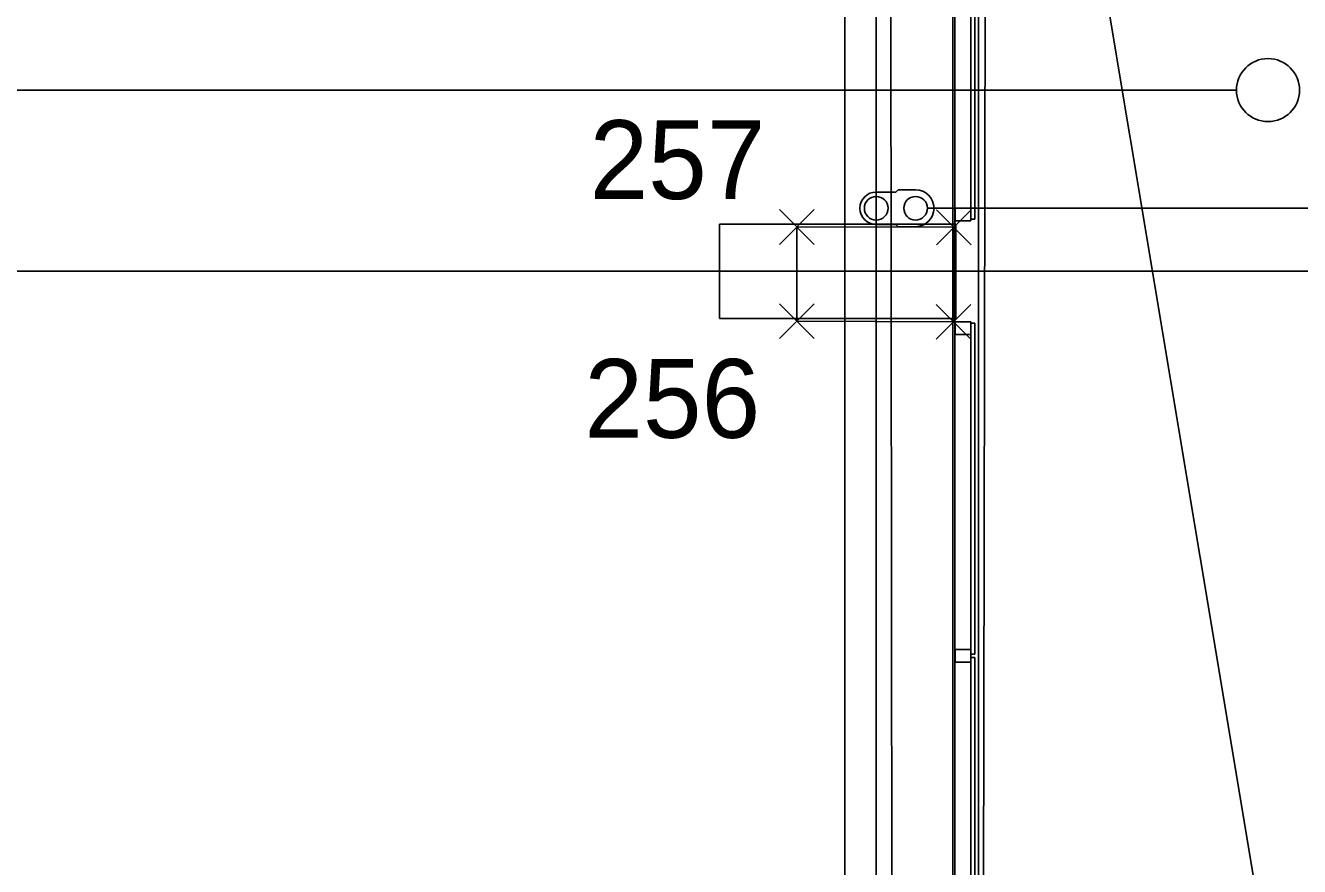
# Model space of a CAD drawing. Extents: x -264205 to -263659, y -1242401 to -1242060.
# Drawn here: x -263800.94 to -263792.86, y -1242178.66 to -1242173.32 of the extents above; entities that cross this region are included whole.
import ezdxf

# ---------------------------------------------------------------- set-up
doc = ezdxf.new("R2010")
doc.units = 0
for name, color, linetype in [('BOD_CISLO', 7, 'Continuous'), ('BOD_SYMBOL', 7, 'Continuous'), ('KFA_SO_10-1_BETONOVE_STLPY', 7, 'Continuous'), ('KFA_SO_10-1_PLACHTY', 7, 'Continuous'), ('KFA_SO_10-1_STRECHY', 7, 'Continuous'), ('KFA_SO_10-1_TRIBUNA_C_OBVOD', 7, 'Continuous'), ('OBRUBNIKY_KOMUNIKACIE_PROJEKT', 7, 'Continuous'), ('OSI_STAVBY_KFA', 7, 'Continuous'), ('SITUACIA_DSP_2D', 7, 'Continuous')]:
    doc.layers.add(name, color=color, linetype=linetype)

msp = doc.modelspace()

# ---------------------------------------------------------------- linework, layer by layer
at = {"layer": 'BOD_SYMBOL'}
for p, q in [((-263796.1565, -1242174.7115), (-263795.9355, -1242174.4905)), ((-263795.9355, -1242174.7115), (-263796.1565, -1242174.4905)), ((-263795.1605, -1242174.7135), (-263794.9395, -1242174.4925)), ((-263794.9395, -1242174.7135), (-263795.1605, -1242174.4925)), ((-263796.1565, -1242175.3095), (-263795.9355, -1242175.0885)), ((-263795.9355, -1242175.3095), (-263796.1565, -1242175.0885)), ((-263795.1625, -1242175.3135), (-263794.9415, -1242175.0925)), ((-263794.9415, -1242175.3135), (-263795.1625, -1242175.0925))]:
    msp.add_line(p, q, dxfattribs=at)
at = {"layer": 'KFA_SO_10-1_BETONOVE_STLPY'}
msp.add_lwpolyline([(-263795.05, -1242174.603), (-263795.052, -1242175.203), (-263796.046, -1242175.199), (-263796.046, -1242174.601)], close=True, dxfattribs=at)
at = {"layer": 'KFA_SO_10-1_PLACHTY'}
msp.add_line((-263794.893, -1242195.596), (-263794.843, -1242168.189), dxfattribs=at)
for points in [[(-263795.396, -1242226.823), (-263795.427, -1242195.892), (-263795.456, -1242167.905), (-263795.427, -1242160.909), (-263795.402, -1242132.887), (-263795.428, -1242101.98)], [(-263790.3646, -1242195.4172), (-263794.826, -1242168.6678), (-263794.862, -1242168.412)]]:
    msp.add_lwpolyline(points, dxfattribs=at)
at = {"layer": 'KFA_SO_10-1_STRECHY'}
msp.add_line((-263795.734, -1242227.196), (-263795.754, -1242101.588), dxfattribs=at)
at = {"layer": 'KFA_SO_10-1_TRIBUNA_C_OBVOD'}
msp.add_lwpolyline([(-263795.284, -1242101.267), (-263795.051, -1242101.819), (-263795.059, -1242226.991), (-263795.286, -1242227.548)], dxfattribs=at)
at = {"layer": 'OBRUBNIKY_KOMUNIKACIE_PROJEKT'}
msp.add_line((-263794.8928, -1242101.3822), (-263794.8928, -1242227.3822), dxfattribs=at)
at = {"layer": 'OSI_STAVBY_KFA'}
for p, q in [((-263795.5428, -1242083.2372), (-263795.5428, -1242246.7072)), ((-263792.6528, -1242174.8822), (-263909.3428, -1242174.8822))]:
    msp.add_line(p, q, dxfattribs=at)
at = {"layer": 'SITUACIA_DSP_2D'}
for p, q in [((-263794.8928, -1242101.3822), (-263794.8928, -1242227.3822)), ((-263795.0428, -1242101.7691), (-263795.0428, -1242226.9954)), ((-263794.9427, -1242174.5523), (-263794.9427, -1242172.4523)), ((-263794.9177, -1242172.4523), (-263794.9177, -1242174.5523)), ((-263801.5928, -1242173.7322), (-263800.5928, -1242173.7322)), ((-263800.5928, -1242173.7322), (-263793.2566, -1242173.7322)), ((-263795.5428, -1242174.3792), (-263795.4178, -1242174.3792)), ((-263795.4178, -1242174.3792), (-263795.4038, -1242174.3652)), ((-263795.2928, -1242174.3652), (-263795.4038, -1242174.3652)), ((-263795.4038, -1242174.3652), (-263795.2928, -1242174.3652)), ((-263795.2178, -1242174.4822), (-263790.4163, -1242174.4822)), ((-263794.9427, -1242174.4823), (-263795.0427, -1242174.4823)), ((-263795.0427, -1242174.4823), (-263795.0427, -1242174.5623)), ((-263794.9427, -1242174.5223), (-263794.9427, -1242174.4823)), ((-263794.9427, -1242174.5623), (-263794.9427, -1242174.5223)), ((-263795.0378, -1242174.5823), (-263796.5378, -1242174.5823)), ((-263796.5378, -1242174.5823), (-263796.5378, -1242175.1823)), ((-263795.5428, -1242174.5852), (-263795.4178, -1242174.5852)), ((-263795.4178, -1242174.5852), (-263795.4038, -1242174.5992)), ((-263795.4038, -1242174.5992), (-263795.2928, -1242174.5992)), ((-263795.0427, -1242174.5623), (-263794.9427, -1242174.5623)), ((-263795.0378, -1242175.1823), (-263795.0378, -1242174.5823)), ((-263794.9177, -1242174.5523), (-263794.9427, -1242174.5523)), ((-263796.5378, -1242175.1823), (-263795.0378, -1242175.1823)), ((-263795.0427, -1242175.2823), (-263795.0427, -1242175.2023)), ((-263795.0427, -1242175.2023), (-263794.9427, -1242175.2023)), ((-263794.9427, -1242175.2023), (-263794.9427, -1242175.2423)), ((-263794.9177, -1242175.2123), (-263794.9427, -1242175.2123)), ((-263794.9427, -1242175.2123), (-263794.9427, -1242177.3123)), ((-263794.9427, -1242175.2423), (-263794.9427, -1242175.2823)), ((-263794.9177, -1242177.3123), (-263794.9177, -1242175.2123)), ((-263794.9427, -1242175.2823), (-263795.0427, -1242175.2823)), ((-263795.0427, -1242177.3623), (-263795.0427, -1242177.2823)), ((-263795.0427, -1242177.2823), (-263794.9427, -1242177.2823)), ((-263794.9427, -1242177.2823), (-263794.9427, -1242177.3223)), ((-263794.9427, -1242177.3623), (-263795.0427, -1242177.3623)), ((-263794.9427, -1242177.3123), (-263794.9177, -1242177.3123)), ((-263794.9427, -1242177.3223), (-263794.9427, -1242177.3623)), ((-263794.9427, -1242179.4323), (-263794.9427, -1242177.3323)), ((-263794.9427, -1242177.3323), (-263794.9177, -1242177.3323)), ((-263794.9177, -1242177.3323), (-263794.9177, -1242179.4323))]:
    msp.add_line(p, q, dxfattribs=at)
for centre, radius in [((-263793.0566, -1242173.7322), 0.2), ((-263795.5428, -1242174.4822), 0.075), ((-263795.2928, -1242174.4822), 0.075)]:
    msp.add_circle(centre, radius, dxfattribs=at)
for centre, radius, start, end in [((-263795.5428, -1242174.4822), 0.103, 90, 270), ((-263795.2928, -1242174.4822), 0.117, 270, 90)]:
    msp.add_arc(centre, radius, start, end, dxfattribs=at)

# ---------------------------------------------------------------- texts
at = {"layer": 'BOD_CISLO'}
for s, p in [('257', (-263797.3616, -1242174.4237)), ('256', (-263797.3945, -1242175.939))]:
    msp.add_text(s, height=0.5, dxfattribs=at).set_placement(p)

doc.saveas('drawing.dxf')
